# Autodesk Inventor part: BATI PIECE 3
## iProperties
Created: 2004-11
Part Number: BATI PIECE 3
Document SubType Name: Modeling
Designer: Bruno
Manufacturer: Standard
Standards Organization: Custom
Author: Bruno
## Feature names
1. Base1
